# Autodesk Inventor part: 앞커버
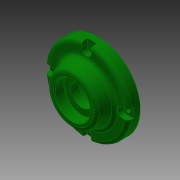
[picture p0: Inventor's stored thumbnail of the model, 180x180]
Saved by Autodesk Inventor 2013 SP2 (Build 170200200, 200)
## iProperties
Created: 2017-08
Part Number: 앞커버
Material: 알루미늄 6061
Document SubType Name: Modeling
Designer: mduedu
Density: 1 g/cm^3
Author: mduedu
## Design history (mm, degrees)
sketch "스케치1"
  geometry: C1 r 35 at (0, 0); 1 further point
  constraints: 1 centre point, 1 coincident
  dimensions: "d0" = 70 diameter of C1
extrude "돌출1" new body sketch "스케치1" distance "d1" = 10; taper "d2" = 0 deg
sketch "스케치2"
  geometry: C1 r 24 at (0, 0); 1 further point
  constraints: 1 centre point, 1 coincident
  dimensions: "d3" = 48 diameter of C1
node "작업 평면1"
sketch "스케치3"
  geometry: C1 r 20 at (0, 0); 1 further point
  constraints: 1 centre point, 1 coincident
  dimensions: "d5" = 40 diameter of C1
feature "로프트1" sketch "스케치3" dims "d6" = 0, "d7" = 90 deg, "d8" = 0, "d9" = 90 deg
sketch "스케치4"
  geometry: C1 r 24 at (0, 0) reference; 1 further point
extrude "돌출2" join sketch "스케치4" distance "d10" = 8; taper "d11" = 0 deg
hole "구멍1" diameter "d14" = 40; stored, may be unused: countersink angle "d18" = 90 deg, drill point angle "d20" = 0 deg; dims "d12" = 10, "d13" = 10, "d15" = 6, "d16" = 4, "d17" = 2, "d19" = 12
hole "구멍2" diameter "d23" = 34; stored, may be unused: countersink angle "d27" = 90 deg, drill point angle "d29" = 0 deg; dims "d21" = 10, "d22" = 10, "d24" = 6, "d25" = 4, "d26" = 2, "d28" = 3
hole "구멍3" diameter "d32" = 19; stored, may be unused: countersink angle "d36" = 90 deg, drill point angle "d38" = 0 deg; dims "d30" = 10, "d31" = 10, "d33" = 6, "d34" = 4, "d35" = 2, "d37" = 3
chamfer "모따기1" distance "d39" = 1; stored, may be unused: second distance "d40" = 2, angle "d41" = 45 deg
sketch "스케치5"
  geometry: C1 r 15 at (0, 0); 1 further point
  constraints: 1 centre point, 1 coincident
  dimensions: "d42" = 30 diameter of C1
extrude "돌출3" cut sketch "스케치5" distance "d43" = 8.3; taper "d44" = 0 deg
chamfer "모따기2" distance "d47" = 0.8; stored, may be unused: second distance "d48" = 2, angle "d49" = 30 deg
fillet "모깎기1" dims "d50" = 0.3
fillet "모깎기2" dims "d51" = 0.3
fillet "모깎기3" dims "d52" = 3
fillet "모깎기4" dims "d79" = 3
sketch "스케치6" dims "d53" = 58
  geometry: 6 further points
  constraints: 2 vertical alignment, 1 coincident, 7 other
  dimensions: "d56" = 360 deg dimension on point (0, 0) point (0, 29) (derived)
sketch "스케치9" dims "d93" = 62
  geometry: C1 r 35 at (0, 0) reference; 3 further points
  constraints: 2 vertical alignment, 1 coincident, 2 other
hole "구멍6" sketch "스케치9" at (0, 31) diameter "d72" = 4.5; stored, may be unused: countersink angle "d76" = 90 deg, drill point angle "d78" = 0 deg; dims "d73" = 6, "d74" = 8, "d75" = 4.6, "d77" = 8
fillet "모깎기5" dims "d80" = 3
fillet "모깎기6" dims "d81" = 3
sketch "스케치10"
  geometry: L1 (-4, 31)-(4, 31); L2 (4, 31)-(4, 38); L3 (4, 38)-(-4, 38); L4 (-4, 38)-(-4, 31); 6 further points
  constraints: 8 end point, 2 parallel, 1 horizontal, 1 midpoint, 1 perpendicular, 4 other
  dimensions: "d98" = 7 distance of L1.end L2.end
extrude "돌출4" cut sketch "스케치10" stored distance "d88" = 10; taper "d89" = 0 deg
node "솔리드1"
pattern_circular "원형 패턴2" dims angle "d96" = 360 deg
pattern_circular "원형 패턴1" dims angle "d91" = 360 deg
other parameters: "d4" = 12
